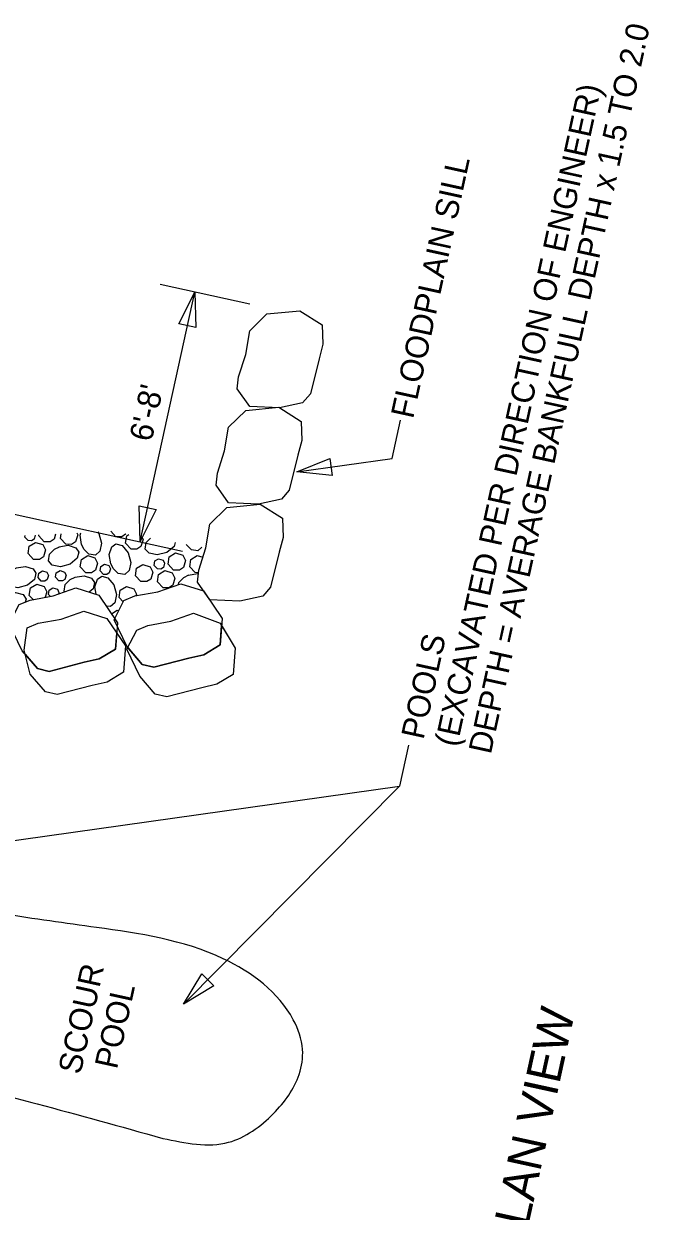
# Model space of a CAD drawing. Extents: x 2126110 to 2128246, y 1804858 to 1811658.
# Drawn here: x 2127054 to 2127598, y 1809146 to 1810179 of the extents above; entities that cross this region are included whole.
import ezdxf

# ---------------------------------------------------------------- set-up
doc = ezdxf.new("R2010")
doc.units = 0
for name, color, linetype in [('1', 7, 'Continuous'), ('DET-EARTH', 7, 'Continuous'), ('Old_Level_1', 7, 'Continuous'), ('Old_Level_41', 7, 'Continuous')]:
    doc.layers.add(name, color=color, linetype=linetype)

msp = doc.modelspace()

# ---------------------------------------------------------------- linework, layer by layer
at = {"layer": '1'}
for p, q in [((2127250.3, 1809935), (2127172.2, 1809952.1)), ((2127154.9, 1809728.6), (2127202.3, 1809945.5)), ((2127374, 1809800.8), (2127381.3, 1809834.2)), ((2127291, 1809789.1), (2127374, 1809800.8)), ((2126752.4, 1809427.2), (2127380.5, 1809515.8)), ((2127192.6, 1809326), (2127380.5, 1809515.8))]:
    msp.add_line(p, q, dxfattribs=at)
for points in [[(2127188.6, 1809917.8), (2127202.3, 1809945.5), (2127203.2, 1809914.6)], [(2127321.8, 1809785.9), (2127291, 1809789.1), (2127319.7, 1809800.7)], [(2127168.7, 1809756.3), (2127154.9, 1809728.6), (2127154, 1809759.5)], [(2127219, 1809342), (2127192.6, 1809326), (2127208.4, 1809352.6)]]:
    msp.add_lwpolyline(points, close=True, dxfattribs=at)
at = {"layer": 'DET-EARTH'}
for p, q in [((2127191.6, 1809719.9), (2126360, 1809901.6)), ((2127388.3, 1809551.4), (2127380.5, 1809515.8))]:
    msp.add_line(p, q, dxfattribs=at)
for points in [[(2127059.1, 1809677.6), (2127079.2, 1809681.4), (2127099, 1809688.2), (2127118.8, 1809681.9), (2127135, 1809657.9), (2127133.4, 1809635), (2127119.1, 1809626.6), (2127106.1, 1809623.5), (2127075.7, 1809615.6), (2127065.6, 1809618), (2127052.3, 1809633.4), (2127052.3, 1809633.4), (2127041, 1809656.9), (2127049.5, 1809673.6), (2127059.1, 1809677.6)], [(2127150.2, 1809681.2), (2127170.3, 1809684.9), (2127190.1, 1809691.8), (2127209.9, 1809685.5), (2127226.1, 1809661.5), (2127224.5, 1809638.6), (2127210.1, 1809630.1), (2127197.2, 1809627), (2127166.8, 1809619.2), (2127156.7, 1809621.5), (2127143.4, 1809637), (2127143.4, 1809637), (2127132.1, 1809660.4), (2127140.6, 1809677.2), (2127150.2, 1809681.2)], [(2127066.1, 1809657.4), (2127086.1, 1809661.1), (2127105.9, 1809668), (2127125.8, 1809661.7), (2127142, 1809637.7), (2127140.3, 1809614.8), (2127126, 1809606.3), (2127113.1, 1809603.2), (2127082.7, 1809595.4), (2127072.6, 1809597.7), (2127059.2, 1809613.2), (2127059.2, 1809613.2), (2127053.9, 1809634.1), (2127056.4, 1809653.4), (2127066.1, 1809657.4)], [(2127161.5, 1809655.5), (2127181.5, 1809659.3), (2127201.3, 1809666.1), (2127224.3, 1809657.6), (2127237.4, 1809635.8), (2127235.7, 1809612.9), (2127221.4, 1809604.5), (2127208.5, 1809601.4), (2127178.1, 1809593.5), (2127168, 1809595.8), (2127154.6, 1809611.3), (2127154.6, 1809611.3), (2127143.3, 1809634.8), (2127151.8, 1809651.5), (2127161.5, 1809655.5)]]:
    msp.add_lwpolyline(points, dxfattribs=at)
msp.add_spline([(2127174.5, 1809209.4), (2127065.1, 1809239.4), (2126993.6, 1809260.2), (2126924.8, 1809309.7), (2126924.4, 1809349.4), (2126960.4, 1809402.6), (2127034.1, 1809404.8), (2127116.9, 1809392.8), (2127227, 1809365.7), (2127288, 1809312.6), (2127296.1, 1809286.8), (2127293.1, 1809265.1), (2127270.8, 1809231), (2127231.8, 1809206), (2127174.5, 1809209.4)], degree=3, dxfattribs=at)
at = {"layer": 'Old_Level_1'}
for p, q in [((2127133.7, 1809732.7), (2127129.3, 1809737.4)), ((2127205.5, 1809701.4), (2127202.7, 1809701.5)), ((2127209.3, 1809686.4), (2127208.9, 1809686.2))]:
    msp.add_line(p, q, dxfattribs=at)
for points in [[(2127057.3, 1809729.3), (2127054.5, 1809732.4), (2127054.7, 1809733.7)], [(2127063.5, 1809734.1), (2127062.5, 1809730.6), (2127060.4, 1809729.2), (2127057.3, 1809729.3)], [(2127071.3, 1809728.3), (2127066.6, 1809733.5), (2127066.7, 1809734.3)], [(2127081.2, 1809735), (2127079.9, 1809730.5), (2127076.4, 1809728.2), (2127071.3, 1809728.3)], [(2127090.2, 1809726.1), (2127085.4, 1809731.2), (2127086.1, 1809735.3)], [(2127099.7, 1809736), (2127100.5, 1809734.4), (2127098.7, 1809728.3), (2127095.2, 1809725.9), (2127090.2, 1809726.1)], [(2127103.8, 1809726), (2127102.5, 1809734), (2127103.2, 1809736.2)], [(2127117.9, 1809736.9), (2127119, 1809735.6), (2127121.1, 1809727.2), (2127119.7, 1809720.1), (2127115.9, 1809716.7), (2127110.2, 1809717.6), (2127105.8, 1809721.9), (2127103.7, 1809726.3)], [(2127142.3, 1809735.2), (2127142.2, 1809734.9), (2127138.8, 1809732.6), (2127133.7, 1809732.7)], [(2127146.9, 1809722), (2127142.2, 1809727.2), (2127143.2, 1809733.5), (2127145, 1809734.7)], [(2127156, 1809732.8), (2127157.3, 1809730.3), (2127155.5, 1809724.2), (2127152, 1809721.9), (2127146.9, 1809722)], [(2127185.2, 1809727.7), (2127184.3, 1809724.2), (2127178.1, 1809719), (2127169.7, 1809716.9), (2127162.6, 1809718.3), (2127159.2, 1809722), (2127160.1, 1809727.8), (2127163.7, 1809731.5)], [(2127062.1, 1809712.9), (2127057.4, 1809718.1), (2127058.4, 1809724.4), (2127063.9, 1809727.8), (2127070.1, 1809725.8), (2127072.5, 1809721.2), (2127070.7, 1809715.1), (2127067.2, 1809712.8), (2127062.1, 1809712.9)], [(2127084.2, 1809723.8), (2127092.2, 1809725.2), (2127098.9, 1809723.1), (2127101.4, 1809719.3), (2127100.1, 1809713.9), (2127093.9, 1809708.7), (2127085.5, 1809706.6), (2127078.4, 1809708), (2127075, 1809711.7), (2127075.9, 1809717.5), (2127080.2, 1809721.8), (2127084.6, 1809724)], [(2127129.3, 1809709.2), (2127128, 1809717.2), (2127130.1, 1809723.8), (2127133.8, 1809726.4), (2127139.3, 1809725.1), (2127144.5, 1809718.8), (2127146.6, 1809710.4), (2127145.2, 1809703.3), (2127141.4, 1809699.9), (2127135.7, 1809700.8), (2127131.3, 1809705.1), (2127129.2, 1809709.5)], [(2127208.6, 1809723.7), (2127205.1, 1809720.5), (2127199.4, 1809721.3), (2127195, 1809725.7), (2127194.8, 1809726)], [(2127107.5, 1809701.4), (2127102.7, 1809706.5), (2127103.7, 1809712.9), (2127109.2, 1809716.3), (2127115.4, 1809714.3), (2127117.8, 1809709.7), (2127116, 1809703.5), (2127112.6, 1809701.2), (2127107.5, 1809701.4)], [(2127122.8, 1809699.9), (2127119.9, 1809703), (2127120.5, 1809706.8), (2127123.8, 1809708.8), (2127127.5, 1809707.6), (2127129, 1809704.9), (2127127.9, 1809701.2), (2127125.8, 1809699.8), (2127122.8, 1809699.9)], [(2127155.4, 1809693.7), (2127150.7, 1809698.8), (2127151.7, 1809705.2), (2127157.2, 1809708.6), (2127163.4, 1809706.6), (2127165.8, 1809702), (2127164, 1809695.9), (2127160.5, 1809693.6), (2127155.4, 1809693.7)], [(2127169.9, 1809704.7), (2127167, 1809707.8), (2127167.6, 1809711.6), (2127170.9, 1809713.6), (2127174.7, 1809712.4), (2127176.1, 1809709.7), (2127175, 1809706), (2127172.9, 1809704.6), (2127169.9, 1809704.7)], [(2127183.9, 1809703.7), (2127179.1, 1809708.9), (2127180.1, 1809715.3), (2127185.6, 1809718.7), (2127191.9, 1809716.6), (2127194.2, 1809712.1), (2127192.4, 1809705.9), (2127189, 1809703.6), (2127183.9, 1809703.7)], [(2127202.7, 1809701.5), (2127198, 1809706.6), (2127199, 1809713), (2127204.5, 1809716.4), (2127209.4, 1809714.8)], [(2127047, 1809705.6), (2127055, 1809706.9), (2127061.7, 1809704.9), (2127064.2, 1809701.1), (2127062.9, 1809695.6), (2127056.7, 1809690.5), (2127048.3, 1809688.3), (2127041.2, 1809689.8), (2127037.8, 1809693.5), (2127038.6, 1809699.2), (2127043, 1809703.6), (2127047.4, 1809705.7)], [(2127068.8, 1809694.1), (2127066, 1809697.2), (2127066.6, 1809701), (2127069.9, 1809703.1), (2127073.6, 1809701.9), (2127075, 1809699.1), (2127074, 1809695.4), (2127071.9, 1809694.1), (2127068.8, 1809694.1)], [(2127084.2, 1809694.3), (2127081.3, 1809697.4), (2127081.9, 1809701.2), (2127085.2, 1809703.2), (2127088.9, 1809702), (2127090.4, 1809699.2), (2127089.3, 1809695.6), (2127087.2, 1809694.2), (2127084.2, 1809694.3)], [(2127098, 1809697.5), (2127106, 1809698.8), (2127112.6, 1809696.7), (2127115.2, 1809693), (2127113.9, 1809687.5), (2127110.4, 1809684.6)], [(2127116.6, 1809682.6), (2127115.5, 1809689.1), (2127117.6, 1809695.8), (2127121.4, 1809698.3), (2127126.8, 1809697), (2127132, 1809690.8), (2127134.1, 1809682.4), (2127132.7, 1809675.3), (2127129, 1809671.9), (2127125.4, 1809672.4)], [(2127174.7, 1809688.3), (2127169.9, 1809693.5), (2127170.9, 1809699.8), (2127176.4, 1809703.2), (2127182.6, 1809701.2), (2127185, 1809696.6), (2127183.2, 1809690.5), (2127179.7, 1809688.2), (2127174.7, 1809688.3)], [(2127188.1, 1809691.1), (2127188.4, 1809692.9), (2127192.7, 1809697.2), (2127197.1, 1809699.4)], [(2127196.8, 1809699.3), (2127204.8, 1809700.6), (2127205.4, 1809700.4)], [(2127061.8, 1809678.1), (2127058.4, 1809681.7), (2127059.5, 1809688.1), (2127064.9, 1809691.5), (2127071.2, 1809689.5), (2127073.5, 1809684.9), (2127072.1, 1809680)], [(2127076.6, 1809680.9), (2127075.1, 1809682.4), (2127075.8, 1809686.3), (2127079, 1809688.3), (2127082.8, 1809687.1), (2127084.2, 1809684.3), (2127083.8, 1809683)], [(2127089.2, 1809684.8), (2127088.7, 1809685.3), (2127089.6, 1809691.1), (2127093.9, 1809695.5), (2127098.3, 1809697.6)], [(2127139.9, 1809676), (2127136.5, 1809679.7), (2127137.5, 1809686.1), (2127143, 1809689.4), (2127149.2, 1809687.4), (2127151.6, 1809682.8), (2127151.2, 1809681.4)], [(2127038.4, 1809683), (2127046.4, 1809684.3), (2127053, 1809682.3), (2127055.6, 1809678.5), (2127054.9, 1809675.9)], [(2127130, 1809665.7), (2127134.9, 1809668.7), (2127136, 1809668.3)]]:
    msp.add_lwpolyline(points, dxfattribs=at)
at = {"layer": 'Old_Level_41'}
for p, q in [((2127133.4, 1809635), (2127134.4, 1809648.9)), ((2127134.4, 1809648.9), (2127142, 1809637.7)), ((2127224.5, 1809638.6), (2127225.7, 1809655.4)), ((2127225.7, 1809655.4), (2127237.4, 1809635.8)), ((2127142, 1809637.7), (2127140.3, 1809614.8)), ((2127143.3, 1809634.8), (2127144, 1809636.2)), ((2127144, 1809636.2), (2127156.7, 1809621.5)), ((2127210.1, 1809630.1), (2127224.5, 1809638.6)), ((2127059.2, 1809613.2), (2127054.8, 1809630.5)), ((2127054.8, 1809630.5), (2127065.6, 1809618)), ((2127106.1, 1809623.5), (2127119.1, 1809626.6)), ((2127119.1, 1809626.6), (2127133.4, 1809635)), ((2127154.6, 1809611.3), (2127143.3, 1809634.8)), ((2127166.8, 1809619.2), (2127197.2, 1809627)), ((2127197.2, 1809627), (2127210.1, 1809630.1)), ((2127237.4, 1809635.8), (2127235.7, 1809612.9)), ((2127065.6, 1809618), (2127075.7, 1809615.6)), ((2127075.7, 1809615.6), (2127106.1, 1809623.5)), ((2127156.7, 1809621.5), (2127166.8, 1809619.2)), ((2127072.6, 1809597.7), (2127059.2, 1809613.2)), ((2127126, 1809606.3), (2127113.1, 1809603.2)), ((2127140.3, 1809614.8), (2127126, 1809606.3)), ((2127168, 1809595.8), (2127154.6, 1809611.3)), ((2127154.6, 1809611.3), (2127154.6, 1809611.3)), ((2127235.7, 1809612.9), (2127221.4, 1809604.5)), ((2127082.7, 1809595.4), (2127072.6, 1809597.7)), ((2127113.1, 1809603.2), (2127082.7, 1809595.4)), ((2127178.1, 1809593.5), (2127168, 1809595.8)), ((2127208.5, 1809601.4), (2127178.1, 1809593.5)), ((2127221.4, 1809604.5), (2127208.5, 1809601.4))]:
    msp.add_line(p, q, dxfattribs=at)
for points in [[(2127240.4, 1809871.8), (2127246.7, 1809891.2), (2127250.1, 1809911.9), (2127265, 1809926.4), (2127293.8, 1809929.2), (2127313.2, 1809916.9), (2127313.8, 1809900.3), (2127310.4, 1809887.4), (2127302.9, 1809857), (2127296, 1809849.2), (2127276.1, 1809844.8), (2127276.1, 1809844.8), (2127250.1, 1809846), (2127239.3, 1809861.4), (2127240.4, 1809871.8)], [(2127222.1, 1809787.9), (2127228.3, 1809807.4), (2127231.7, 1809828), (2127246.7, 1809842.5), (2127275.5, 1809845.3), (2127294.9, 1809833), (2127295.5, 1809816.4), (2127292.1, 1809803.5), (2127284.5, 1809773.1), (2127277.7, 1809765.3), (2127257.8, 1809760.9), (2127257.8, 1809760.9), (2127231.7, 1809762.1), (2127221, 1809777.5), (2127222.1, 1809787.9)], [(2127205.8, 1809703.6), (2127212, 1809723.1), (2127215.4, 1809743.7), (2127230.3, 1809758.2), (2127259.2, 1809761), (2127278.5, 1809748.7), (2127279.2, 1809732.1), (2127275.7, 1809719.2), (2127268.2, 1809688.8), (2127261.4, 1809681), (2127241.4, 1809676.6), (2127241.4, 1809676.6), (2127215.4, 1809677.8), (2127204.7, 1809693.2), (2127205.8, 1809703.6)], [(2127059.1, 1809677.6), (2127079.2, 1809681.4), (2127099, 1809688.2), (2127118.8, 1809681.9), (2127135, 1809657.9), (2127133.4, 1809635), (2127119.1, 1809626.6), (2127106.1, 1809623.5), (2127075.7, 1809615.6), (2127065.6, 1809618), (2127052.3, 1809633.4), (2127052.3, 1809633.4), (2127041, 1809656.9), (2127049.5, 1809673.6), (2127059.1, 1809677.6)], [(2127150.2, 1809681.2), (2127170.3, 1809684.9), (2127190.1, 1809691.8), (2127209.9, 1809685.5), (2127226.1, 1809661.5), (2127224.5, 1809638.6), (2127210.1, 1809630.1), (2127197.2, 1809627), (2127166.8, 1809619.2), (2127156.7, 1809621.5), (2127143.4, 1809637), (2127143.4, 1809637), (2127132.1, 1809660.4), (2127140.6, 1809677.2), (2127150.2, 1809681.2)]]:
    msp.add_lwpolyline(points, dxfattribs=at)

# ---------------------------------------------------------------- texts
at = {"layer": 'DET-EARTH'}
for s, height, p in [('DEPTH = AVERAGE BANKFULL DEPTH x 1.5 TO 2.0', 20, (2127459.8, 1809542.8)), ('(EXCAVATED PER DIRECTION OF ENGINEER)', 20, (2127430.5, 1809549.2)), ('FLOODPLAIN SILL', 20, (2127392.2, 1809834.6)), ("6'-8'", 20, (2127164.7, 1809814.6)), ('POOLS', 20, (2127401.2, 1809555.6)), ('SCOUR', 20, (2127102.9, 1809264.3)), ('POOL', 20, (2127134.6, 1809268.9)), ('PLAN VIEW', 30, (2127486.5, 1809105.7))]:
    msp.add_text(s, height=height, rotation=77.6736, dxfattribs=at).set_placement(p)

doc.saveas('drawing.dxf')
